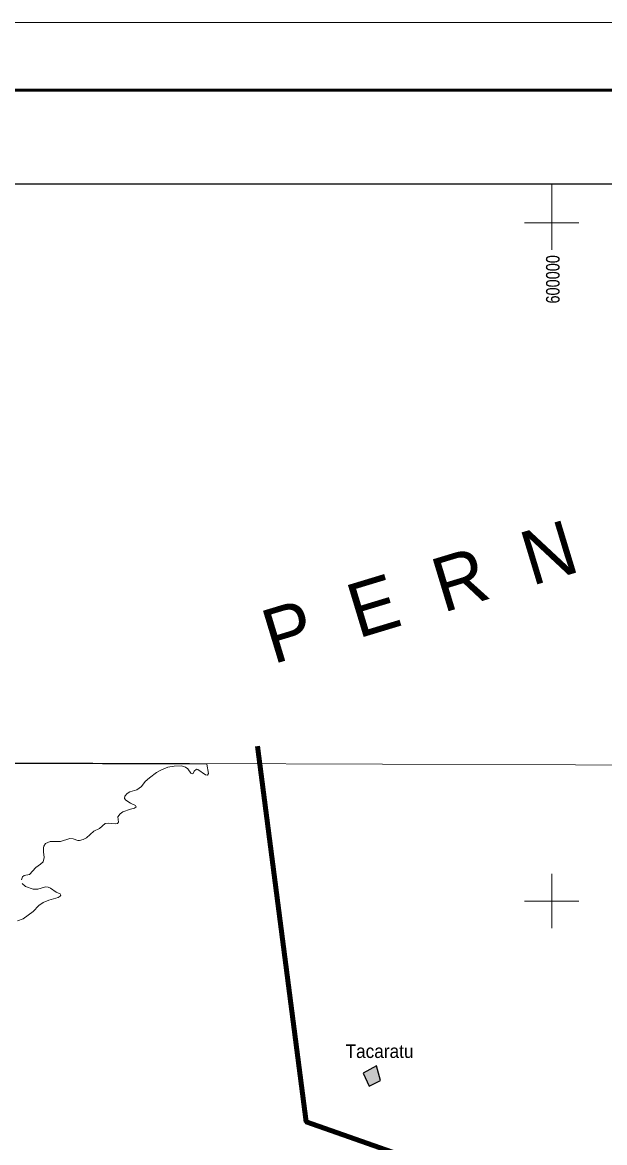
# Model space of a CAD drawing. Extents: x 553962 to 842807, y 8883888 to 9032388.
# Drawn here: x 580496 to 601949, y 8991098 to 9032388 of the extents above; entities that cross this region are included whole.
import ezdxf
from ezdxf.enums import TextEntityAlignment as Align

# ---------------------------------------------------------------- set-up
doc = ezdxf.new("R2010")
doc.units = 0
doc.header["$LTSCALE"] = 200
for name, color, linetype, lineweight in [('1', 7, 'Continuous', 13), ('2', 7, 'Continuous', 13), ('21', 7, 'Continuous', 25), ('25', 7, 'Continuous', 13), ('3', 7, 'Continuous', 13), ('9', 7, 'Continuous', 90)]:
    doc.layers.add(name, color=color, linetype=linetype, lineweight=lineweight)
for name, color, linetype in [('41', 7, 'Continuous'), ('42', 7, 'Continuous'), ('47', 7, 'Continuous')]:
    doc.layers.add(name, color=color, linetype=linetype)

msp = doc.modelspace()

# ---------------------------------------------------------------- hatches: boundary and pattern name
at = {"layer": '21'}
msp.add_hatch(color=256, dxfattribs=at).paths.add_polyline_path([(593047.1, 8993652.8), (593274.2, 8993173.1), (593688.7, 8993391.5), (593540, 8993932.9)])

# ---------------------------------------------------------------- linework, layer by layer
at = {"layer": '1'}
msp.add_lwpolyline([(565303.2, 9005146.6), (664889.8, 9004806.7), (719872.1, 9004543.9), (790635.8, 9004109)], dxfattribs=at)
at = {"layer": '2'}
for p, q in [((600000, 9024000), (600000, 9026438.8)), ((599000, 9025000), (601000, 9025000)), ((600000, 8999000), (600000, 9001000)), ((599000, 9000000), (601000, 9000000))]:
    msp.add_line(p, q, dxfattribs=at)
at = {"layer": '21'}
msp.add_lwpolyline([(593047.1, 8993652.8), (593274.2, 8993173.1), (593688.7, 8993391.5), (593540, 8993932.9)], close=True, dxfattribs=at)
at = {"layer": '25'}
msp.add_line((587296.7, 9005052), (574348.1, 9005079.3), dxfattribs=at)
for points in [[(580463.4, 9000778.4), (580500.2, 9000888.6), (580562.8, 9000942.6), (580759.6, 9000984), (580990.8, 9001234.6), (581168, 9001360), (581260.1, 9001451.7), (581298.8, 9001611), (581269.7, 9001811.5), (581267.5, 9001967.7), (581280.6, 9002023.8), (581345.4, 9002123), (581515.4, 9002200.7), (581905.2, 9002198.8), (582242.4, 9002304.6), (582365.5, 9002291.2), (582536.5, 9002231.2), (582601.1, 9002231.2), (582739.9, 9002272.4), (582854.4, 9002335.1), (583124.7, 9002577.1), (583340.8, 9002674.5), (583541.9, 9002858.1), (583651.7, 9002877.5), (583929.3, 9002846), (584004.2, 9002858.1), (584030.8, 9002904.2), (584017.3, 9003104.5), (584099.4, 9003216.9), (584192.4, 9003289.2), (584481.8, 9003391.9), (584629.6, 9003423.7), (584682.7, 9003471.9), (584658.6, 9003520.2), (584473.2, 9003604), (584302.8, 9003722.6), (584259.5, 9003783.3), (584268.2, 9003872.1), (584354.7, 9003962.9), (584458.5, 9004027.7), (584711.2, 9004098.9), (584888.4, 9004222.2), (585025.2, 9004408.7), (585173.7, 9004544.1), (585437.6, 9004740.9), (585593, 9004823), (585860.5, 9004930.9), (586094, 9004976.5), (586360.6, 9004989.5), (586505.2, 9004940), (586587.3, 9004879.5), (586702.2, 9004719.4), (586749.8, 9004689.2), (586792.6, 9004706), (586819.4, 9004784.7), (586914.3, 9004864.1), (586966.1, 9004855.3), (587240.7, 9004654.4), (587315.8, 9004635.1), (587350.6, 9004699.9), (587296.7, 9005052)], [(580463.4, 9000778.4), (580500.2, 9000888.6), (580562.8, 9000942.6), (580759.6, 9000984), (580990.8, 9001234.6), (581168, 9001360), (581260.1, 9001451.7), (581298.8, 9001611), (581269.7, 9001811.5), (581267.5, 9001967.7), (581280.6, 9002023.8), (581345.4, 9002123), (581515.4, 9002200.7), (581905.2, 9002198.8), (582242.4, 9002304.6), (582365.5, 9002291.2), (582536.5, 9002231.2), (582601.1, 9002231.2), (582739.9, 9002272.4), (582854.4, 9002335.1), (583124.7, 9002577.1), (583340.8, 9002674.5), (583541.9, 9002858.1), (583651.7, 9002877.5), (583929.3, 9002846), (584004.2, 9002858.1), (584030.8, 9002904.2), (584017.3, 9003104.5), (584099.4, 9003216.9), (584192.4, 9003289.2), (584481.8, 9003391.9), (584629.6, 9003423.7), (584682.7, 9003471.9), (584658.6, 9003520.2), (584473.2, 9003604), (584302.8, 9003722.6), (584259.5, 9003783.3), (584268.2, 9003872.1), (584354.7, 9003962.9), (584458.5, 9004027.7), (584711.2, 9004098.9), (584888.4, 9004222.2), (585025.2, 9004408.7), (585173.7, 9004544.1), (585437.6, 9004740.9), (585593, 9004823), (585860.5, 9004930.9), (586094, 9004976.5), (586360.6, 9004989.5), (586505.2, 9004940), (586587.3, 9004879.5), (586702.2, 9004719.4), (586749.8, 9004689.2), (586792.6, 9004706), (586819.4, 9004784.7), (586914.3, 9004864.1), (586966.1, 9004855.3), (587240.7, 9004654.4), (587315.8, 9004635.1), (587350.6, 9004699.9), (587296.7, 9005052)], [(580318.7, 8999271.8), (580526.2, 8999343.3), (580889.2, 8999621.9), (581105.3, 8999831.3), (581265.1, 8999950.3), (581472.9, 9000039.1), (581818.5, 9000129.8), (581887.7, 9000186), (581907.3, 9000221.2), (581887.7, 9000272.6), (581740.7, 9000331.1), (581525, 9000480), (581446.9, 9000516.8), (581343.2, 9000525.5), (581066.4, 9000443.4), (580893.5, 9000437), (580608.7, 9000531.7), (580484.7, 9000649.6)], [(580318.7, 8999271.8), (580526.2, 8999343.3), (580889.2, 8999621.9), (581105.3, 8999831.3), (581265.1, 8999950.3), (581472.9, 9000039.1), (581818.5, 9000129.8), (581887.7, 9000186), (581907.3, 9000221.2), (581887.7, 9000272.6), (581740.7, 9000331.1), (581525, 9000480), (581446.9, 9000516.8), (581343.2, 9000525.5), (581066.4, 9000443.4), (580893.5, 9000437), (580608.7, 9000531.7), (580484.7, 9000649.6)]]:
    msp.add_lwpolyline(points, dxfattribs=at)
at = {"layer": '3'}
msp.add_lwpolyline([(842807.3, 9032387.8), (842807.3, 8883887.8), (553961.7, 8883887.8), (553961.7, 9032387.8)], close=True, dxfattribs=at)
at = {"layer": '3', "lineweight": 53}
msp.add_lwpolyline([(840307.3, 9029887.8), (840307.3, 8886387.8), (560211.7, 8886387.8), (560211.7, 9029887.8)], close=True, dxfattribs=at)
at = {"layer": '3', "lineweight": 25}
msp.add_lwpolyline([(563033.9, 9026438.8), (793061.1, 9026438.8), (793495.6, 8889836.8), (563468.3, 8889836.8)], close=True, dxfattribs=at)
at = {"layer": '9'}
msp.add_lwpolyline([(605873.8, 8986618.4), (590956.6, 8991866.7), (589163, 9005713.7)], dxfattribs=at)

# ---------------------------------------------------------------- texts
at = {"layer": '41', "width": 0.95}
msp.add_text('Tacaratu', height=500, dxfattribs=at).set_placement((592402.2, 8994216.5))
at = {"layer": '42'}
msp.add_text('P  E  R  N  A  M  B  U  C  O', height=2000, rotation=16.855, dxfattribs=at).set_placement((589730.9, 9008723.5))
at = {"layer": '47', "width": 0.8}
msp.add_text('600000', height=500, rotation=90, dxfattribs=at).set_placement((600290.6, 9022917.4), align=Align.CENTER)

doc.saveas('drawing.dxf')
